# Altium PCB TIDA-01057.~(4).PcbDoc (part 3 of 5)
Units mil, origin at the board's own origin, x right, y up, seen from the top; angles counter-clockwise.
Board outline 4448 x 3930 mil, 4 copper layers (Layer 1 - Top Layer, Layer 2 - GND, Layer 3 - PWR, Layer 4 - Bottom Layer), stack 59.034 mil thick; 537 components, 284 nets, 1540 pads, 770 vias.
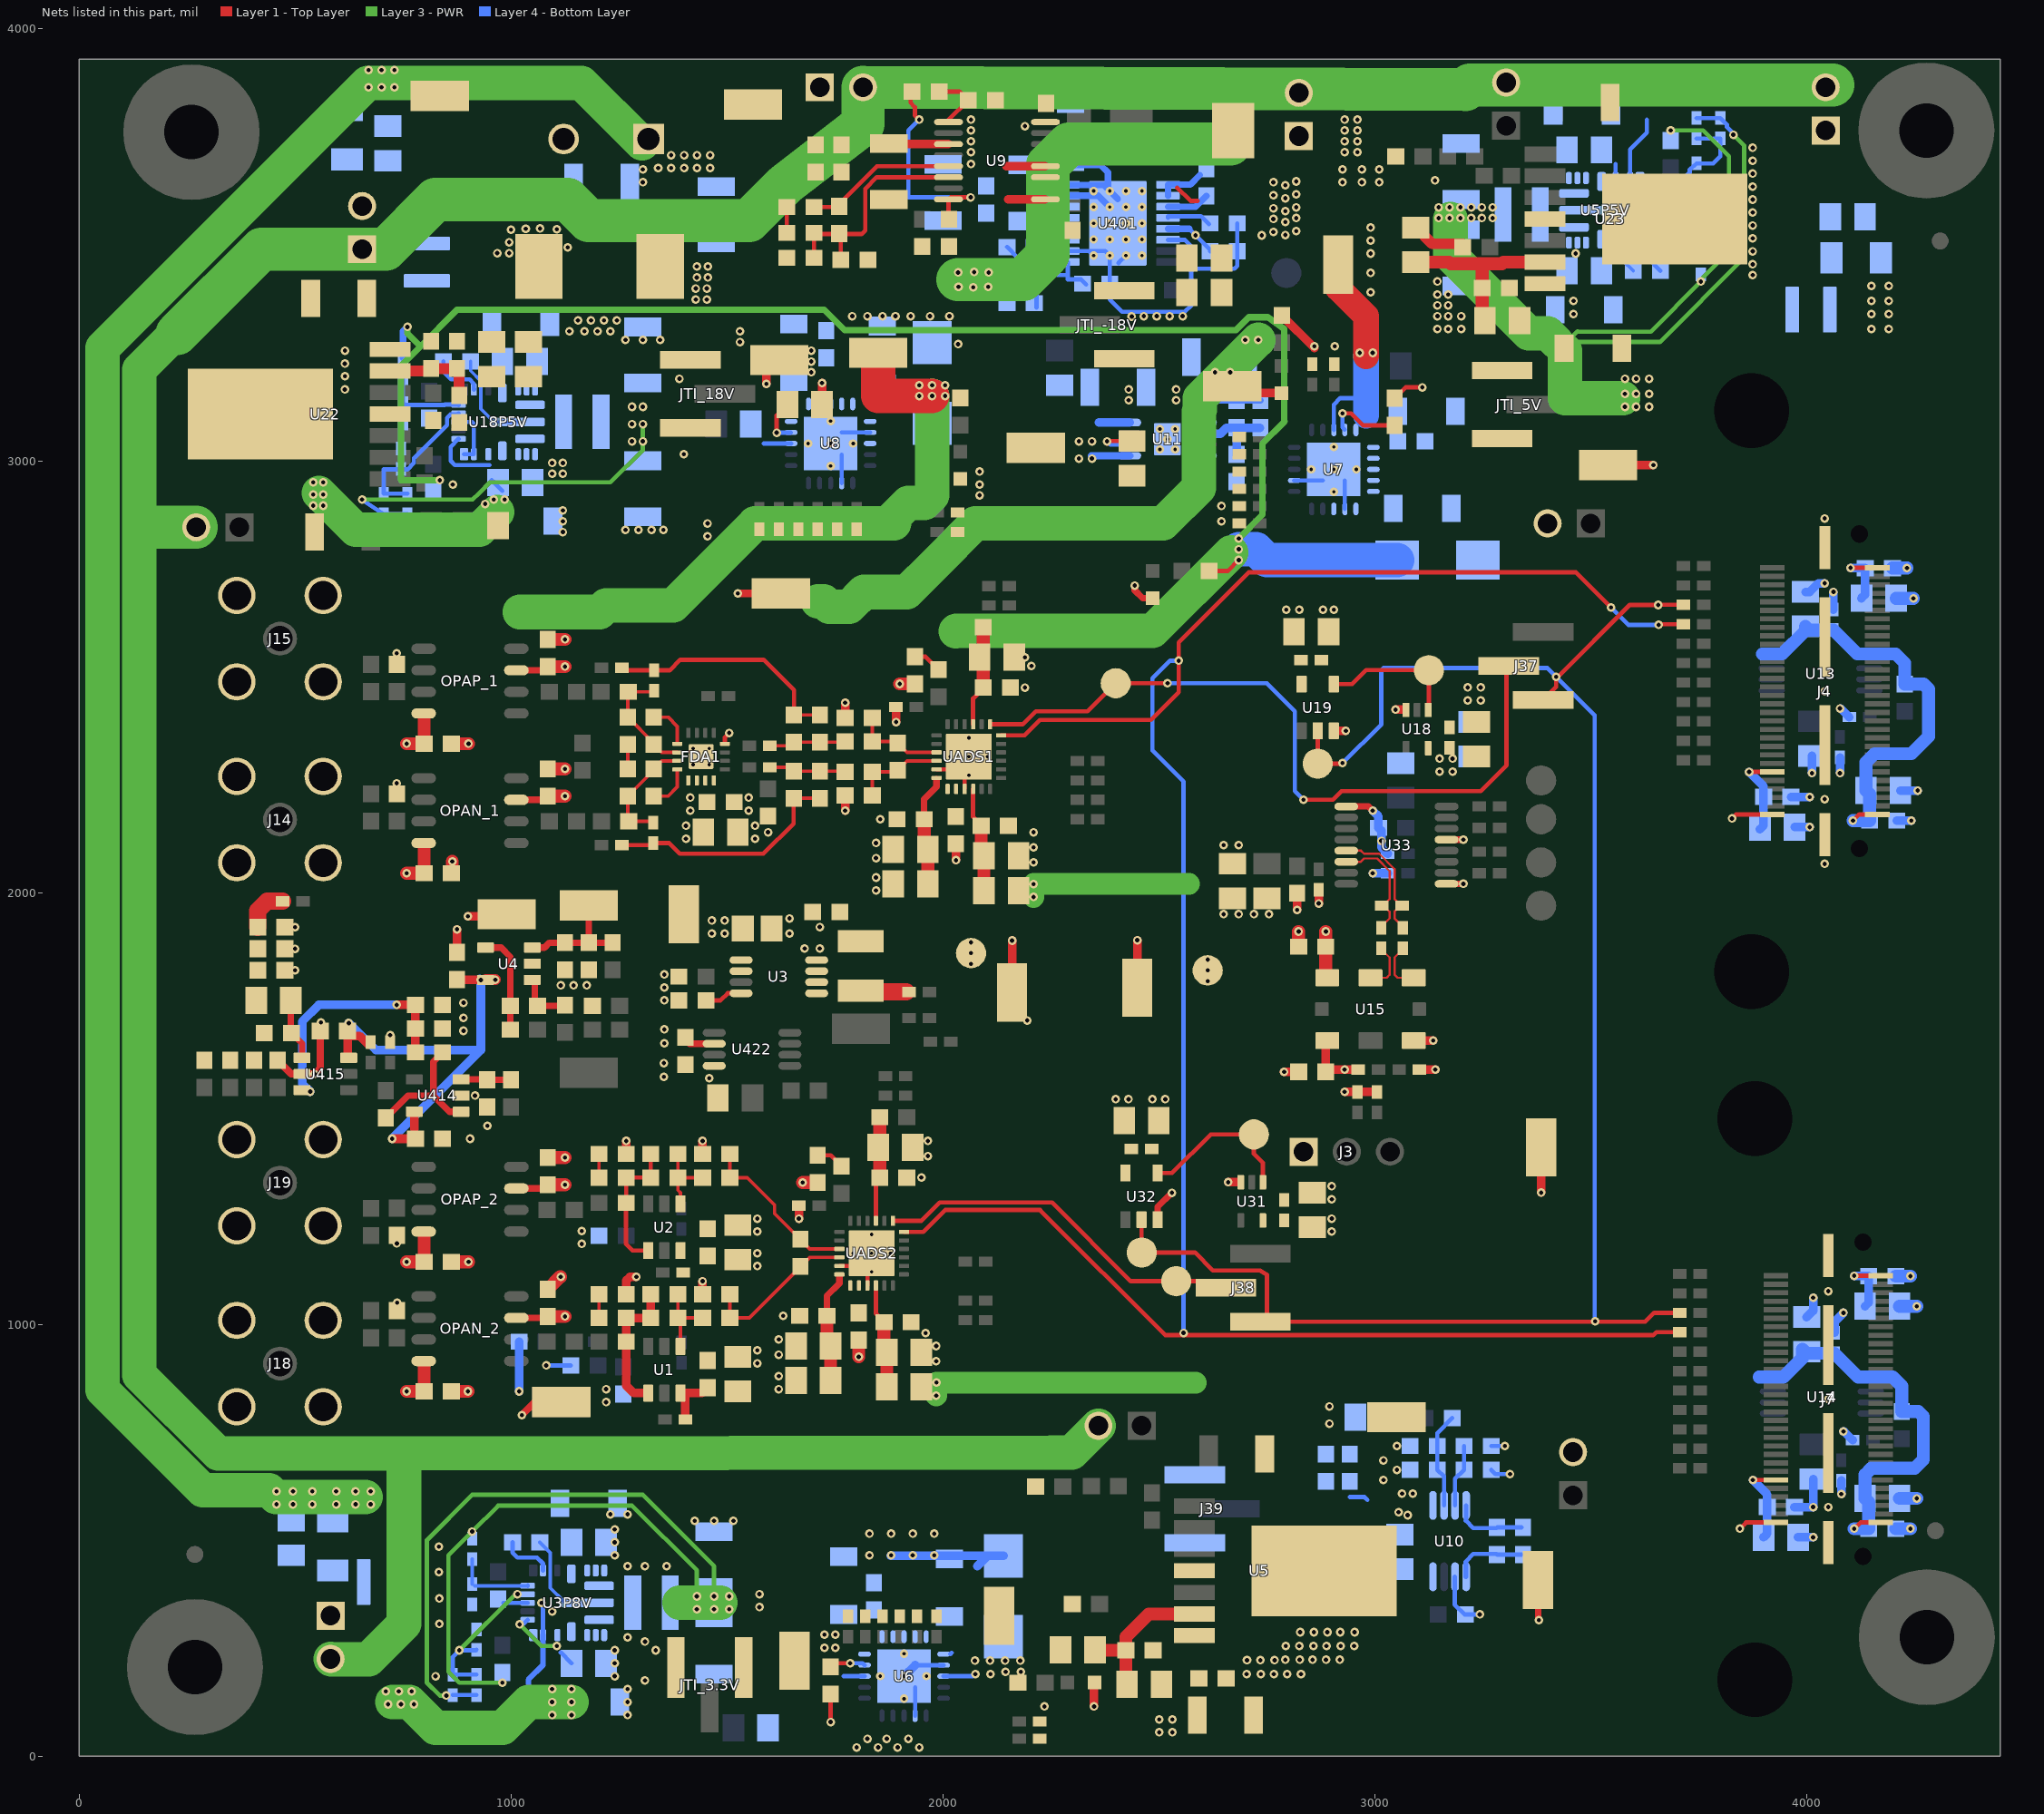
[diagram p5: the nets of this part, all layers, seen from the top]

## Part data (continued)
U422: "Low Noise, Very Low Drift, Precision Voltage Reference, -40 to 125 degC, 8-pin MSOP (DGK), Green (RoHS & no Sb/Br)", Alternate Manufacturer="Texas Instruments", Alternate PartNumber=Equivalent, Rating=Catalog, Supplier Part Number 1=296-24502-2-ND, Temp Coeff(Max)(ppm/ degree C)=3
UADS1 UADS2: "20-Bit, High-Speed SAR ADCs With Integrated Reference Buffer, Integrated LDO, and multiSPI Digital Interface, RGE0024H (VQFN-24)", Alternate Manufacturer="Texas Instruments", Alternate PartNumber=ADS8900BRGET
ZZ2 ZZ3 ZZ4: library part AssemblyNote, Alternate Manufacturer=-

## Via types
v1: diameter 20, hole 10, Layer 1 - Top Layer to Layer 4 - Bottom Layer, tented both sides, 382 vias
v2: diameter 20, hole 10, Layer 1 - Top Layer to Layer 4 - Bottom Layer, 258 vias
v3: diameter 20, hole 10, Layer 1 - Top Layer to Layer 4 - Bottom Layer, tented bottom, 57 vias
v4: diameter 19.68, hole 7.87, Layer 1 - Top Layer to Layer 4 - Bottom Layer, tented both sides, 48 vias
v5: diameter 20, hole 10, Layer 1 - Top Layer to Layer 4 - Bottom Layer, tented top, 19 vias
v6: diameter 19.68, hole 7.87, Layer 1 - Top Layer to Layer 4 - Bottom Layer, 6 vias

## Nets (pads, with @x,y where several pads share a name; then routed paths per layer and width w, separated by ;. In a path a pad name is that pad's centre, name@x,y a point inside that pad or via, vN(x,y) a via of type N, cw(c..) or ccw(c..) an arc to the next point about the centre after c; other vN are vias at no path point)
3.3V: C20.1 C61.1 C62.1 C94.2 C95.2 C290.1 C291.2 C338.1 C343.1 C344.2 C345.2 C346.2 C347.1 C353.1 L4.2 L7.1 L9.1 L10.2 L12.2 R46.2 R88.2 R89.2 R91.1 TP_3P3V.1 U6.1 U6.3 U6.20 U15.1@2890,1656.91 U15.6@2890,1802.58 U18.5 U19.5 U31.5 U32.5 | length 1429.3
  Layer 1 - Top Layer w20: U15.1@2886.5,1653.41 C62.1@2886.5,1584.75 2891.5,1589.75 v1(2930,1589.75) R91.1@2961.38,1589.75 ; v1(2930,1538.37) R88.2@2960,1538.37 R89.2@3005,1538.37
  Layer 1 - Top Layer w30: v1(2886.5,1909.74) C61.1@2886.5,1874.74 2886.5,1806.08 U15.6@2890,1802.58
  Layer 3 - PWR w50: v1(1984.45,834.74) 1984.45,864.19 v1(1985.25,865) 2585,865 ; v1(2210,1989.75) v1(2210,2019.75) 2210.25,2020 2570,2020
  Layer 4 - Bottom Layer w10: U6.3@2001.54,185 2070,185 v1(2075,190) ; 2017.09,236.18 2020,239.09
  other v1: 2110,190 2145.02,195 2180.21,195.21 2073.93,221.07 2108.93,221.07 2143.93,221.07 2178.93,221.07 3076.04,558 3055,565 2900.21,1214.75 2900.21,1244.75 2399.83,1521.3 2429.83,1521.3 2650,1949.74 2685,1949.74 2720,1949.74 2755,1949.74 3150,2280.04 3180,2280.04 3150,2310.04 3180,2310.04 2795,2654.75 2825,2654.75
3.8V: C17.1 C18.1 L19.2 TP_3P8V.1 U6.13 U6.15 U6.16 | length 48.5
  Layer 4 - Bottom Layer w10: 1770,185 U6.13@1818.46,185
  other v1: 1725.51,251 1751,251 1725.51,281 1751,281
5.5V: C13.1 C14.1 L18.2 TP_5P5V.1 U7.13 U7.15 U7.16 | length 441.6
  Layer 1 - Top Layer w60: TP_5P5V.1@2915,3400 2980,3335 2980,3242.5
  Layer 4 - Bottom Layer w10: U7.13@2905,3071.54 2905,3130 2920,3145 2960,3145
  Layer 4 - Bottom Layer w60: 2980,3105 L18.2@2980,3220 L18.2@2980,3242.5
  other v3: 2965,3250 2995,3250
5V: C3.2 C16.1 C85.1 C112.2 C116.2 C284.1 C304.1 C305.1 C320.2 C352.1 C449.2 C455.2 CR479.1 FDA1.5 FDA1.6 FDA1.7 FDA1.8 FDA1.12 L6.1 L8.1 R47.2 R453.1 RB18.2 REN0.1 REN1.1 RES18V.1 TP8.1 U1.6 U2.6 U3.1 U3.2 U4.5 U7.1 U7.3 U7.20 U414.5 U415.6 U422.2 | length 5611.6
  Layer 1 - Top Layer w10: U4.5@940.87,1797.6 U4.5@941.34,1798.08 ; FDA1.12@1495.12,2345.75 1495.12,2359.86 v1(1505,2369.75) ; R47.2@2616.5,2745 2660,2745 v1(2685,2770)
  Layer 1 - Top Layer w15: CR479.1@1413.8,1649.8 U422.2@1470.4,1649.8
  Layer 1 - Top Layer w20: C449.2@621.32,1679.02 C449.2@621.53,1678.81 ; U415.6@621.53,1616.87 C449.2@621.53,1678.81 ; R453.1@669.83,1647.64 649.46,1668 632.34,1668 C449.2@621.53,1678.81 ; v2(724.51,1429.75) C455.2@778.5,1429.75 ; 775.87,1452.38 U414.5@775.87,1492.34 ; C320.2@875,1796.24 876.36,1797.6 v1(930,1797.6) ; U1.6@1392.4,840.61 1442.36,840.61 C112.2@1455,853.25 ; REN0.1@1403.62,779.75 U1.6@1403.62,828.37
  Layer 1 - Top Layer w25: U4.5@941.34,1798.08 v1(963.52,1798.08)
  Layer 3 - PWR w15: v3(760,3310) 760,3295 790,3265 ; v2(835,2955) 745,2955 745,3220 790,3265 ; v1(2685,2820) 2740,2875 2740,3040 2789.9,3089.9 ; 2791.19,3091.19 2789.9,3089.9 ; 790,3265 875,3350 1725,3350 1772.5,3302.5 2678.25,3302.5 2708.25,3332.5 2751.75,3332.5 2789.9,3305.9 2789.9,3089.9
  Layer 3 - PWR w80: 2030,2604.75 2031.02,2605.77 2485.9,2605.77 2667.41,2787.28
  Layer 4 - Bottom Layer w15: RB18.2@750,3238.62 750,3300 v3(760,3310)
  Layer 4 - Bottom Layer w20: v2(624.28,1697.72) 686.76,1635.24 930,1635.24 ; v2(724.51,1429.75) 930,1635.24 ; v1@927.86,1799.75 v1(930,1797.6) 930,1635.24
  Layer 4 - Bottom Layer w80: v1(2685,2795) 2725,2795 2750,2770 C352.1@3051.5,2770
  other v1: 1620,849.75 1620,879.75 1570,1134.75 1570,1164.75 1464.79,1905.16 1494.79,1905.16 1464.79,1935.16 1494.79,1935.16 1845,2004.75 1845,2034.75 1405,2124.75 1405,2154.75 1415,2189.75 1415,2219.75
  other v2: 1355,1651 1355,1683
18.5V: C9.1 C10.1 L16.1 TP_18P5V.1 U8.13 U8.15 U8.16 | length 130.9
  Layer 1 - Top Layer w20: v2(1591,3178) 1591,3203 TP_18P5V.1@1621,3233
  Layer 4 - Bottom Layer w10: 1585,3040 U8.13@1648.46,3040
  other v2: 1695,3205 1695,3230 1695,3255
1050_3.3V: Cff3.1 Cout5.1 Cout6.1 JTI_3.3V.3 Rfbt3.2 U5.7
  other v2: 1800,20 1850,20 1895,20 1945,20 1825,40 1870,40 1920,40 2501,55 2531,55 2501,85 2531,85
1050_5V: Cff2.1 Cout4.1 JTI_5V.3 Rfbt2.2 U23.7
1050_18V: Cff.1 Cout1.1 Cout2.1 Cout3.1 JTI_18V.3 Rfbt.2 U22.7
1050_-18V: C34.2 C35.2 C37.2 C41.2 C42.2 C43.2 JTI_-18V.1 R42.1 R50.1 U9.9 U9.12 | length 176
  Layer 1 - Top Layer w20: 2147.2,3682.2 U9.12@2237.2,3682.2 ; 2151.2,3605.43 U9.9@2237.2,3605.43
+18V: C12.1 C79.2 C81.2 C104.2 C106.2 C351.1 OPAN_1.7 OPAN_2.7 OPAP_1.7 OPAP_2.7 R247.2 TP3.1 U8.1 U8.3 U8.20 | length 1981.4
  Layer 1 - Top Layer w15: OPAN_2.7@1012.28,1014.75 1081.5,1014.75 C104.2@1085,1018.25 ; OPAP_2.7@1012.28,1314.75 1081.5,1314.75 C106.2@1085,1318.25 ; OPAN_1.7@1012.28,2214.74 1076.5,2214.74 C81.2@1085,2223.25 ; OPAP_1.7@1012.28,2514.75 1076.5,2514.75 C79.2@1085,2523.25
  Layer 1 - Top Layer w30: C104.2@1085,1018.25 v1(1125,1018.25) ; C106.2@1085,1323.25 v1(1125,1323.25) ; C81.2@1085,2223.25 v1(1125,2223.25) ; C79.2@1085,2523.25 v1(1125,2523.25)
  Layer 1 - Top Layer w80: TP3.1@1850,3240 1850,3150 v1(1945,3150) v1(1975,3150)
  Layer 3 - PWR w80: 1020,2649.75 1205,2649.75 1220.25,2665 1375,2665 1565,2855 1887,2855 1887,2869.78 1919.22,2902 1957,2902 1975,2920 v1(1975,3150)
  other v1: 2005,3150 1945,3175 1975,3175 2005,3175
+24VDC: Cin.1 D1.1 JMTI_-18V.2 JPRI_-18V.2 JSI_3.3V.2 JSI_5V.2 JSI_18V.1 JZI_3.3V.2 JZI_5V.2 JZI_18V.2 | length 9642
  Layer 3 - PWR w10: 1810,3775 1815,3780
  Layer 3 - PWR w80: 227,3295 223,3295 139,3211 139,883 321.47,700.53 569.85,700.53 569.98,700.66 752,700.91 752,306 670,224 583,224 JSI_3.3V.2@582,225 ; 759,700.92 2250,703 2298,703 JZI_3.3V.2@2360,765
  Layer 3 - PWR w100: 149,2844 151,2846 JZI_18V.2@271,2846 ; 227,3295 422,3490 JSI_18V.1@655,3490 710,3490 825,3605 1131,3605 1180,3556 1551,3556 1635,3640 1810,3775 ; 1815,3780 JMTI_-18V.2@1815,3865 3210,3860 3220,3870 JSI_5V.2@4060,3870
  other v1: 1427.8,3373.53 1453.28,3373.53 1427.8,3399.02 1453.28,3399.02 1430,3424.51 1455.49,3424.51 1430,3450 1455.49,3450
+24VDC_IN: 24Vin.1 C1.1 D1.2 J8.2
  other v1: 968,3481 995.62,3481 1131,3494 995.62,3506 1000,3535 1106,3536 1034,3537 1067,3538
-0.2V: C23.1 C24.1 J39.1 L5.1 TP27.1
  other v1: 2895,770 2895,810
-18.5V: C354.1 L17.1 TP25.1 U11.5 U11.8 | length 159.8
  Layer 4 - Bottom Layer w17: v5@2343.39,3011.61 U11.5@2432.4,3011.61
  Layer 4 - Bottom Layer w20: 2361.61,3088.39 U11.8@2432.4,3088.39
  other v2: 2315,3045
  other v3: 2315,3005
  other v5: 2345,3005 2345,3045
-18V: C46.1 C47.1 C80.2 C82.2 C105.2 C107.2 D21.1 OPAN_1.4 OPAN_2.4 OPAP_1.4 OPAP_2.4 R43.2 TP26.1 U11.1 | length 2075.2
  Layer 1 - Top Layer w10: TP26.1@2695,3170 TP26.1@2708.26,3156.74
  Layer 1 - Top Layer w20: TP26.1@2708.26,3156.74 D21.1@2783.32,3156.74
  Layer 1 - Top Layer w30: v1(758.5,844.75) C105.2@798.5,844.75 OPAN_2.4@798.5,909.75 ; v1(758.5,1144.75) C107.2@798.5,1144.75 OPAP_2.4@798.5,1209.75 ; v1(758.5,2044.74) C82.2@798.5,2044.74 OPAN_1.4@798.5,2109.74 ; v1(758.5,2344.75) C80.2@798.5,2344.75 OPAP_1.4@798.5,2409.75
  Layer 3 - PWR w80: 1710,2674.75 1724.22,2674.75 1737.22,2661.75 1782.78,2661.75 1817.04,2696 1916,2696 1979.89,2759.89 2075,2855 2510,2855 2592.56,2937.56 2592.56,3114.78 2595,3117.22 2595,3145 v1(2730,3280)
  Layer 4 - Bottom Layer w15: 2629.55,3139.55 C46.1@2735,3139.55
  Layer 4 - Bottom Layer w20: U11.1@2607.6,3094.29 2607.6,3101.44 2607.6,3117.6 2629.55,3139.55
  other v2: 2700,3280
  other v5: 2630,3205 2665,3205
AGND: C3.1 C4.2 C71.1 C72.1 C79.1 C80.1 C81.1 C82.1 C84.2 C85.2 C88.1 C89.2 C90.2 C91.1 C92.2 C93.2 C96.1 C97.1 C104.1 C105.1 C106.1 C107.1 C108.2 C109.2 C112.1 C115.2 C116.1 C117.2 C118.2 C119.2 C120.1 C121.2 C122.2 C284.2 C287.2 C288.2 C289.2 C304.2 C305.2 C306.2 C307.2 C308.2 C318.2 C320.1 C321.2 C449.1 C453.2 C454.2 C455.1 C457.2 C458.2 C459.2 CR479.2 CR481.2 FDA1.17 J14.2 J14.3 J14.4 J14.5 J15.2 J15.3 J15.4 J15.5 J18.2 J18.3 J18.4 J18.5 J19.2 J19.3 J19.4 J19.5 NT1.1 NT2.1 R3.1 R4.2 R110.1 R112.1 R113.1 R217.1 R268.1 R269.1 R284.1 R288.1 R454.1 R488.1 R491.1 TPAGND1.1 TPAGND2.1 TPAGND3.1 TPAGND4.1 TPAGND.1 U3.7 U3.8 U4.2 U414.2 U415.2 U422.4 UADS1.11 UADS1.15 UADS1.25 UADS2.11 UADS2.15 UADS2.25 | length 1836.9
  Layer 1 - Top Layer w10: UADS2.11@1760.2,1135.22 UADS2.25@1805.47,1135.22 ; UADS2.15@1825.16,1089.94 UADS2.25@1825.16,1154.9 ; UADS1.11@1985.2,2285.22 2030.47,2285.22 UADS1.25@2050.16,2304.9 ; UADS1.15@2050.16,2239.94 UADS1.25@2050.16,2304.9 ; v4(2060,2314.75) UADS1.25@2050.16,2304.9
  Layer 1 - Top Layer w17: R491.1@459.7,1611.24 491.2,1579.75 U415.2@515.87,1579.75 ; U415.2@513.26,1579.47 545.28,1579.47 558.33,1592.52 C449.1@558.33,1679.02 ; v1(1025,789.75) 1055,819.75 TPAGND4.1@1116.5,819.75 ; v2(1525,2692.75) TPAGND1.1@1625,2692.75
  Layer 1 - Top Layer w20: C320.1@875,1861.24 v1(875,1914.75) ; v1(900,1944.75) TPAGND3.1@1000,1944.75 ; R113.1@1266.5,1069.75 1266.5,1101.24 1275,1109.75 v1(1290,1109.75) ; R112.1@1266.5,1394.75 v5(1266.5,1424.75) ; C118.2@1443.5,1069.75 v1(1443.5,1099.75) ; C117.2@1443.5,1394.75 v1(1443.5,1424.75) ; v1(1666.38,1244.75) R288.1@1666.38,1274.75 ; v1(1773.5,2189.75) C89.2@1773.5,2224.75 ; C90.2@1773.5,2404.75 v1(1773.5,2439.75) ; v1(1891.38,2394.75) R284.1@1891.38,2429.75 ; v1(2030,2074.75) C88.1@2030,2113.25 ; TPAGND2.1@2160,1788.75 v1(2160,1888.75)
  Layer 1 - Top Layer w30: C105.1@861.5,844.75 v1(900,844.75) ; C107.1@861.5,1144.75 v1(901.5,1144.75) ; C82.1@861.49,2044.74 863.99,2047.25 v1(863.99,2071.94) ; C80.1@861.5,2344.75 v1(901.5,2344.75) ; C104.1@1085,1081.24 1113.5,1109.75 v1(1115,1109.75) ; C106.1@1085,1386.24 v1(1125,1386.24) ; C81.1@1085,2286.24 v1(1125,2286.24) ; C79.1@1085,2586.24 v1(1125,2586.24) ; v1(1675,1328.25) R269.1@1710,1328.25 ; v1(1805,924.75) C119.2@1805,963.25 ; v1(1900,2483.25) R268.1@1935,2483.25
  Layer 4 - Bottom Layer w10: v1(1081.5,904.75) R110.1@1138.5,904.75
  Layer 4 - Bottom Layer w20: v1(1018.5,844.75) 1018.5,904.75 C108.2@1018.5,959.75
  other v1: 1220,819.75 1220,849.75 1570,909.75 1984.45,914.74 1620,929.75 1570,939.75 1984.45,949.74 1620,964.75 1960,979.75 1630,1019.75 1163.5,1186.24 735.46,1187.35 1570,1214.75 1163.5,1216.24 1570,1244.75 1950,1339.75 1965,1389.75 1965,1424.75 2195,1703.75 1354.79,1750.16 1354.79,1780.16 1115,1785.01 1145,1785.01 1175,1785.01 1354.79,1810.16 2065,1834.75 2065,1859.75 1679.79,1870.16 1714.79,1870.16 2065,1884.75 1644.79,1905.16 1714.79,1920.16 1644.79,1940.16 2210,2069.75 1845,2079.75 2210,2104.75 1845,2114.75 1565,2124.75 1595,2139.75 2210,2139.75 1565,2154.75 1855,2169.75 1550,2189.75 1550,2219.75 2190,2474.75 2205,2524.75 2190,2544.75
  other v2: 905,1429.75 1459,1570 1354,1573 1354,1605 890,1679.75 559.83,1699.02 890,1709.75 500,1819.75 500,1869.75 500,1919.75
  other v4: 1835,1121.44 1791.69,1164.75 1835,1164.75 1878.31,1164.75 1835,1208.05 2060,2271.44 1421.3,2296.04 1458.7,2296.04 2016.69,2314.75 2103.31,2314.75 1421.3,2333.45 1458.7,2333.45 2060,2358.05
  other v5: 736,1050 945,1459.75 916.46,1529.75 545,1579.75 720,1669.75 890,1744.75 735,2253 735,2554
BCLK0_N: C64.1 U15.5@2990,1802.58 | length 116.9
  Layer 1 - Top Layer w5: U15.5@2990,1802.58 3027.33,1802.58 3034.5,1809.75 3034.5,1849.25 3015,1868.75 C64.1@3015,1871.12
BCLK0_P: C63.1 U15.4@3090,1802.58 | length 116.9
  Layer 1 - Top Layer w5: C63.1@3065,1871.13 3065,1868.75 3045.5,1849.25 3045.5,1809.75 3052.67,1802.58 U15.4@3090,1802.58
BCLK1_N: C64.2 R92.1 U33.6 | length 271.2
  Layer 1 - Top Layer w5: U33.6@2933.86,2071.36 2967.62,2071.36 2975,2078.75 3005.44,2078.75 3034.5,2049.68 3034.5,1985.25 R92.1@3019,1969.75 ; C64.2@3015,1918.37 3015,1920.74 3034.5,1940.25 3034.5,1955.25 3020,1969.75 R92.1@3019,1969.75 ; R92.1@3016.38,1969.75 R92.1@3019,1969.75
BCLK1_P: C63.2 R92.2 U33.5 | length 287.9
  Layer 1 - Top Layer w5: U33.5@2933.86,2096.95 2967.8,2096.95 2975,2089.75 3010,2089.75 3045.5,2054.24 3045.5,1985.25 3061,1969.75 R92.2@3063.63,1969.75 ; R92.2@3059,1969.75 3045.5,1956.25 3045.5,1940.25 3065,1920.75 C63.2@3065,1918.37
CONVST: J37.3 J38.3 R67.1 R78.1 TP7.1 TP35.1 U19.2 U32.2 | length 4240.8
  Layer 1 - Top Layer w10: TP35.1@2459.83,1166.75 U32.2@2459.83,1242.14 ; TP35.1@2460.3,1166.28 2583.47,1166.28 2625,1124.75 2734,1124.75 2750,1114.69 2750,1021.04 J38.3@2734.96,1006.01 3626.01,1006.01 3646.69,1026.69 R78.1@3706.4,1026.69 R78.1@3706.35,1026.75 ; U19.2@2867.81,2374.41 TP7.1@2867.81,2298.54 2923.8,2298.54 v2(2925,2299.75) ; J37.3@3389.96,2446.01 3420,2476.04 v2(3420,2499.75) 3423.75,2499.75 3590,2666 v2(3656,2666) 3656.39,2666.39 R67.1@3714.12,2666.39
  Layer 4 - Bottom Layer w10: v2(2925,2299.75) 3015,2389.75 3015,2514.75 3020,2519.75 3400,2519.75 v2(3420,2499.75) 3509,2410.75 3509,1008 v2(3510,1007)
CONVST_TO_DIF_ADC: J37.2 TP1.1 UADS1.1 | length 1720.7
  Layer 1 - Top Layer w10: UADS1.1@2109.21,2389.55 2184.8,2389.55 2215,2419.75 2335,2419.75 TP1.1@2400,2484.75 v1(2520,2484.75) ; v1(2835,2214.75) 2902.63,2214.75 2922.63,2234.75 3245,2234.75 3305,2294.75 3305,2519.71 J37.2@3310.04,2524.75
  Layer 4 - Bottom Layer w10: v1(2520,2484.75) 2750,2484.75 2815,2419.75 2815,2234.75 v1(2835,2214.75)
CONVST_TO_SE_ADC: J38.2 TP4.1 UADS2.1 | length 870.1
  Layer 1 - Top Layer w10: UADS2.1@1884.21,1239.55 1949.8,1239.55 1992.25,1282 2252.75,1282 2435,1099.75 TP4.1@2540,1099.75 2640.04,1099.75 J38.2@2655.04,1084.75
CONVSTN_DIF: TP2.1 U18.1 U19.4 | length 326.1
  Layer 1 - Top Layer w10: U19.4@2905.21,2482.68 2947.64,2482.68 2980,2515.04 TP2.1@3125,2515.04 3125,2424.44 U18.1@3123.4,2422.84
CONVSTN_SE: TP34.1 U31.1 U32.4 | length 379.1
  Layer 1 - Top Layer w10: U32.4@2497.23,1350.41 2530.67,1350.41 2620,1439.75 TP34.1@2720,1439.75 2720,1394.75 2740.8,1373.94 U31.1@2740.8,1329.04
CSN: R68.1 R79.1 UADS1.24 UADS2.24 | length 5423.1
  Layer 1 - Top Layer w10: UADS2.24@1909.8,1213.96 1954.21,1213.96 2005,1264.75 2225,1264.75 2515,974.75 3644.75,974.75 3651.69,981.69 R79.1@3706.4,981.69 ; UADS1.24@2134.8,2363.96 2189.21,2363.96 2225,2399.75 2481.51,2399.75 2546,2464.24 v2(2546,2537) 2546,2579.53 2707.86,2741.39 3465.61,2741.39 v2(3547,2660) ; v2(3657,2620) 3658.39,2621.39 R68.1@3714.12,2621.39 R68.1@3713.73,2621
  Layer 4 - Bottom Layer w10: v2(2546,2537) 2526,2537 2485,2496 2485,2329 2557,2257 v2(2557,980) v2@2557,976 ; v2(3547,2660) 3587,2620 v2(3657,2620)
EVM_DVDD_0: C22.1 C266.1 J4.50 | length 204
  Layer 1 - Top Layer w10: v1(3866.7,2279.29) J4.50@3920.51,2279.29
  Layer 4 - Bottom Layer w20: v1(3866.7,2279.29) 3900.02,2245.96 3900.02,2154.9 C22.1@3891.52,2146.39
EVM_DVDD_1: C21.1 C268.1 J7.50 | length 203.5
  Layer 1 - Top Layer w10: v1(3875.21,639.59) J7.50@3928.52,639.59
  Layer 4 - Bottom Layer w20: v1(3875.21,639.59) 3908.53,606.27 C268.1@3908.53,576.69 3908.53,515.2 C21.1@3900.03,506.69
EVM_ID_PWR_0: C53.2 C58.1 C259.1 C271.1 J4.59 R64.2 U13.1 U13.8 | length 1025.4
  Layer 1 - Top Layer w10: v1(4107.01,2166.39) 4121.4,2180.79 J4.59@4163.51,2180.79
  Layer 4 - Bottom Layer w30: 3897,2552.4 3943,2552.4 3997,2606.4 C271.1@3997,2616.4 4005.63,2607.77 C53.2@4062,2607.77 4117,2552.77 4117,2552.4 4206,2552.4 4227.01,2531.39 R64.2@4227.01,2482.89 4270.51,2482.89 4282.01,2471.39 4282.01,2361.39 4242.01,2321.39 4157.01,2321.39 4137.01,2301.39 C58.1@4137.01,2236.39 4145.51,2227.89 C259.1@4145.51,2166.39 v1(4107.01,2166.39)
EVM_ID_PWR_1: C55.2 C60.1 C260.1 C272.1 J7.59 R87.2 U14.1 U14.8 | length 995.7
  Layer 1 - Top Layer w10: v1(4110.02,526.69) 4124.42,541.09 J7.59@4171.52,541.09
  Layer 4 - Bottom Layer w30: 3890.02,877.69 3946.04,877.69 3990.02,921.68 3990.02,941.69 3998.65,933.07 4063.65,933.07 4119.02,877.69 4199.02,877.69 4220.03,856.69 R87.2@4220.03,798.19 4258.53,798.19 4270.02,786.69 4270.02,686.69 4250.02,666.69 4150.02,666.69 4135.03,651.7 C60.1@4135.03,596.69 4143.54,588.19 C260.1@4143.54,526.69 v1(4110.02,526.69)
EVM_REG_5V5_0: C57.1 C267.1 J4.1 | length 169.3
  Layer 1 - Top Layer w10: v1(4101.51,2752.09) J4.1@4163.51,2752.09
  Layer 4 - Bottom Layer w20: v1(4101.51,2752.09) 4134.34,2752.09 4135.02,2751.4 4135.02,2689.89 C57.1@4126.52,2681.39
EVM_REG_5V5_1: C59.1 C269.1 J7.1 | length 168.8
  Layer 1 - Top Layer w10: v1(4110.02,1112.39) J7.1@4171.52,1112.39
  Layer 4 - Bottom Layer w20: v1(4110.02,1112.39) 4142.85,1112.39 C269.1@4143.54,1111.71 4143.54,1050.2 C59.1@4135.03,1041.69
FB_3P3V: Cff3.2 Rfbb3.2 Rfbt3.1 U5.6 | length 358.8
  Layer 1 - Top Layer w30: Rfbb3.2@2353,245 Rfbt3.1@2423.5,245 ; Cff3.2@2423.5,168.5 Rfbt3.1@2423.5,245 ; U5.6@2582.37,329 2476.5,329 2423.5,276.01 Rfbt3.1@2423.5,245
FB_5V: Cff2.2 Rfbb5.2 Rfbt2.1 U23.6 | length 423.7
  Layer 1 - Top Layer w30: Rfbb5.2@3095,3460 3171.83,3460 3175.53,3456.3 3294.47,3456.3 3298.17,3460 U23.6@3394.37,3460 ; Cff2.2@3248.5,3331.5 Rfbt2.1@3248.5,3400 3248.5,3452.8
FB_18V: Cff.2 Rfbb.2 Rfbt.1 U22.6 | length 213.9
  Layer 1 - Top Layer w25: U22.6@719.63,3208 Rfbt.1@809.5,3208 ; Rfbt.1@815,3213.5 Cff.2@875,3213.5 880,3208.5 Rfbb.2@880,3151.5
GND: C1.2 C9.2 C10.2 C11.2 C12.2 C13.2 C14.2 C15.1 C16.2 C17.2 C18.2 C19.1 C20.2 C21.2 C22.2 C23.2 C24.2 C25.2 C26.2 C27.2 C28.2 C31.2 C32.2 C33.2 C41.1 C42.1 C45.2 C47.2 C53.1 C54.1 C55.1 C56.1 C57.2 C58.2 C59.2 C60.2 C61.2 C62.2 C94.1 C95.1 C259.2 C260.2 C261.2 C262.2 C266.2 C267.2 C268.2 C269.2 C271.2 C272.2 C290.2 C291.1 C338.2 C339.2 C340.2 C343.2 C344.1 C345.1 C346.1 C347.2 C348.2 C349.2 C350.2 C351.2 C352.2 C353.2 C354.2 C355.2 C356.2 C357.2 C358.2 C359.2 C360.2 C362.2 C364.2 C366.2 C367.2 C368.2 C369.2 C370.2 C371.2 C372.2 C375.2 C376.2 C378.2 C379.2 C380.2 C381.2 C382.2 C383.2 C384.2 C388.2 C389.2 C391.2 C401.2 C402.2 C405.1 C406.1 C409.1 Cin1.2 Cin2.2 Cin3.2 Cin.2 Cout1.2 Cout2.2 Cout3.2 Cout4.2 Cout5.2 Cout6.2 Css2.2 Css3.2 Css.1 CVCC3V.2 CVCC5V.2 CVCC18V.2 D14.1 D18.1 D22.1 GNDin.1 J3.1 J4.60 J4.MP1 J4.MP2 J4.MP3 J4.MP4 J5.2 J6.2 J7.60 J7.MP1 J7.MP2 J7.MP3 J7.MP4 J8.1 J39.3 L1.2 L401.2 NT1.2 NT2.2 R8.1 R9.1 R10.1 R11.1 R12.1 R13.1 R14.1 R15.1 R17.1 R18.1 R19.1 R20.1 R21.1 R24.1 R25.1 R26.1 R27.1 R29.1 R30.1 R31.1 R32.1 R33.1 R34.1 R35.1 R36.1 R41.2 R44.1 R90.1 R246.2 R279.1 R280.1 R290.1 R294.1 R297.1 R402.2 Renb2.1 Renb3.1 Renb.1 Rfbb3.1 Rfbb5.1 Rfbb.1 TPGND1.1 TPGND2.1 TPGND3.1 TPGND4.1 TPGND.1 U3P8V.5 U3P8V.6 U3P8V.7 U3P8V.8 U3P8V.10 U3P8V.11 U3P8V.12 U3P8V.13 U3P8V.16 U3P8V.17 U3P8V.20 U5.4 U5.8 U5P5V.5 U5P5V.6 U5P5V.7 U5P5V.8 U5P5V.10 U5P5V.11 U5P5V.12 U5P5V.13 U5P5V.16 U5P5V.17 U5P5V.20 U6.2 U6.7 U6.17 U6.18 U6.19 U6.21 U7.2 U7.7 U7.17 U7.18 U7.19 U7.21 U8.2 U8.7 U8.17 U8.18 U8.19 U8.21 U9.11 U10.2 U10.5 U11.4 U11.9 U15.3@3090,1656.91 U18.3 U18P5V.5 U18P5V.6 U18P5V.7 U18P5V.8 U18P5V.10 U18P5V.11 U18P5V.12 U18P5V.13 U18P5V.16 U18P5V.17 U18P5V.20 U19.3 U22.4 U22.8 U23.4 U23.8 U31.3 U32.3 U33.1 U33.9 U33.13 U401.5 | length 9291.5
  Layer 1 - Top Layer w10: v1(1740,78.98) C19.1@1740,137.48 ; 2542,3633 2573.11,3601.89 2590,3601.89 ; C15.1@3046.02,3145.15 3070.87,3170 v1(3110,3170) ; v1(3827.01,2171.39) 3836.4,2180.79 J4.60@3920.51,2180.79 ; v1(3845.02,526.69) 3859.42,541.09 J7.60@3928.52,541.09
  Layer 1 - Top Layer w15: v1(2444,2711) 2444,2700 2462.5,2681.5 D18.1@2486,2681.5 ; U32.3@2497.23,1242.14 2497.23,1271.98 v1(2530,1304.75) ; U33.1@2933.86,2199.31 2985.43,2199.31 v1(2995,2189.75) ; U33.9@3166.14,2020.18 v1(3205,2020.18) ; U33.13@3166.14,2122.54 v1(3205,2122.54) ; TPGND1.1@3378.02,408 3378.02,316.98 v1(3380,315)
  Layer 1 - Top Layer w20: C11.2@1720,3130 v1(1720,3180) ; v1(2350,115) D14.1@2350,160 ; TPGND2.1@2450,1779.75 v1(2450,1889.75) ; v1(2660.21,1329.04) U31.3@2685.21,1329.04 ; R246.2@2785,3336.5 v5@2860,3261.5 ; v1(2790.01,1584.75) C62.2@2823.5,1584.75 ; v1(2820,1959.75) C339.2@2820,1998.25 ; v1(2870,1974.74) C340.2@2870,2006.13 ; U19.3@2905.21,2374.41 v1(2932.81,2374.41) ; v1(3047.81,2423.57) U18.3@3067.81,2423.57 ; U15.3@3090,1656.91 v1(3135,1656.91) ; R90.1@3103.62,1589.75 v1(3140,1589.75) ; v1(3385,1305) TPGND4.1@3385,1425 ; TPGND3.1@3540,2990 v1(3645,2990)
  Layer 1 - Top Layer w25: Rfbb5.1@3095,3540 3132.5,3502.5 3203.5,3502.5 Css2.2@3203.5,3495
  Layer 1 - Top Layer w30: C61.2@2823.5,1874.74 v1(2823.5,1909.74)
  Layer 3 - PWR w80: 663.55,600 455,600 439.47,615.53 286.26,615.53 54,847.79 54,3261 668,3875 1163.43,3875 J8.1@1303.43,3735
  Layer 4 - Bottom Layer w10: CVCC18V.2@810,3098.5 CVCC18V.2@818.5,3090 ; U18P5V.20@878.46,3090 910,3090 913.9,3086.1 U18P5V.16@913.9,3015.2 U18P5V.17@891.26,3015.2 ; CVCC3V.2@981.81,355 U3P8V.20@1038.46,355 ; v2(1070,355) 1073.9,351.1 U3P8V.16@1073.9,280.2 ; U8.7@1765.59,2948.46 U8.21@1765.59,3014.41 ; U8.21@1765.59,3065.59 U8.2@1831.54,3065.59 ; U6.7@1935.59,93.46 U6.21@1935.59,159.41 ; U6.21@1935.59,210.59 U6.2@2001.54,210.59 ; 2570,3537.2 2618.5,3488.7 C405.1@2618.5,3485 ; U7.7@2813.46,2954.41 U7.21@2879.41,2954.41 ; U7.2@2930.59,2888.46 U7.21@2930.59,2954.41 ; 2941.72,599.98 2976.04,599.98 2983.02,593 ; U10.2@3184.9,415.32 3184.9,350.64 3185.81,349.72 ; U10.2@3185.81,415.32 3185.81,349.72 ; v1(3243.02,328) 3207.53,328 3185.81,349.72 ; C27.2@3269.51,663 3279.51,653 v1(3313.02,653) ; C28.2@3269.51,718 v1(3301.04,718) ; 3591.1,3583.9 3595,3580 U5P5V.20@3626.54,3580 ; U5P5V.16@3591.1,3654.8 3591.1,3721.1 3630,3760 3630,3790 ; CVCC5V.2@3686.5,3580 CVCC5V.2@3695,3571.5
  Layer 4 - Bottom Layer w13: 1040,80 1040,177 1073.9,210.9 U3P8V.16@1073.9,280.2
  Layer 4 - Bottom Layer w15: U401.5@2521.14,3537.2 2570,3537.2
  Layer 4 - Bottom Layer w20: v1@1878.5,463.5 C353.2@2140,463.5 ; v4(1910,185) U6.21@1935.59,210.59 ; 2080,440 C353.2@2103.5,463.5 ; v1(2995,2044.75) C350.2@3029.93,2044.75 ; v1(2995,2189.75) 3008.5,2176.24 C348.2@3008.5,2149.75 3015,2143.25 v1(3015,2119.75) 3015,2104.68 C349.2@3029.93,2089.75 ; C266.2@3963.5,2221.39 v1(4007.01,2221.39) ; C268.2@3971.52,576.69 v1(4015.02,576.69) C261.2@4015.02,641.69 ; C22.2@3972.01,2151.39 v1(4007.01,2151.39) ; C21.2@3980.03,506.69 v1(4015.02,506.69) ; C271.2@3997,2696.4 4007.01,2696.4 4027,2716.39 v1(4041.52,2716.39) ; C272.2@4000.02,1016.69 4015.02,1031.69 v1(4015.02,1061.69) ; v1(4012.01,2276.39) C262.2@4012.01,2316.39 ; C53.1@4062,2655.02 v1(4062,2696.4) ; C55.1@4065.02,980.32 4065.02,1006.69 v1(4085.02,1026.69) ; v1(4077.01,2276.39) C54.1@4077.01,2312.77 ; v1@4078.39,2426.39 R279.1@4098.39,2406.39 ; v1(4080.03,606.7) C56.1@4080.03,638.07 ; v1(4085.02,751.69) 4086.4,751.69 R280.1@4106.4,731.69 ; C259.2@4208.5,2166.39 v1(4242.01,2166.39) ; C58.2@4217.01,2236.39 v1(4257.01,2236.39)
  Layer 4 - Bottom Layer w30: C267.2@4198.5,2751.39 v1(4232.01,2751.39) ; C260.2@4206.53,526.69 v1(4240.04,526.69) ; C269.2@4206.53,1111.71 v1(4240.03,1111.71) ; C57.2@4207.01,2681.39 v1(4247.01,2681.39) ; C60.2@4215.03,596.69 v1(4255.04,596.69) ; C59.2@4215.03,1041.69 v1(4255.04,1041.69)
  other v1: 2235,115 1310,175 1575,345 1575,375 1830,465 1880,465 1930,465 1980,465 1240,495 1830,515 1880,515 1930,515 1980,515 1240,525 1425,545 1470,545 1515,545 1270,560 4050.03,576.7 640,583 675,583 3063.02,608 3088.02,608 457,613 495,613 540,613 595,613 640,613 675,613 3020,639.63 3051.04,663 3020,685 3051.04,718 4050.03,826.7 4050.03,1076.7 2900.21,1289.75 2900.21,1319.75 2484.83,1521.3 2514.83,1521.3 2613,1794.75 2613,1819.75 2613,1844.75 4041.51,2066.39 2650,2109.74 2685,2109.74 4041.51,2216.39 4077.01,2426.39 3215,2445.04 3245,2445.04 4041.52,2466.39 3215,2475.04 3245,2475.04 2880,2654.75 2905,2654.75 1295,2840 1353,2840 1120,2860 4041.51,2866.39 2085,2920 1095,2970 1120,2970 1095,2995 2430,3140 2540,3140 2430,3165 2540,3165 2907,3265 1530,3275 1135,3300 1230,3300 1530,3300 4150,3305 4190,3305 1155,3325 1185,3325 1215,3325 1245,3325 1790,3335 1825,3335 1860,3335 1890,3335 4150,3340 4190,3340 4150,3370 4190,3370 4150,3405 4190,3405 1305,3645 1305,3675 1340.69,3677.89 1370.69,3677.89 1400.69,3677.89 1430.69,3677.89 1460.69,3677.89 1370.69,3707.89 1400.69,3707.89 1430.69,3707.89 1460.69,3707.89 2930,3715 2960,3715 2065,3740 2065,3765 2930,3765 2065,3790 730,3865 670,3905
  other v2: 1270,95 1270,125 1270,155 825,185 2703,190 2736,190 2766,190 2797,190 2829,190 2704,222 2735,222 2768,222 2793,223 2826,223 2856,223 2887,223 2919,223 2794,255 2825,255 2858,255 2888,255 2921,255 2952,255 1310,265 1270,275 2827,287 2859,287 2890,287 2920,287 2953,287 834,306 1095,335 834,365 833,426 1310,440 833,485 1455,2825 1265,2840 1455,2855 865,2945 1120,2995 1400,3015 615,3165 615.3,3196 615,3225 615.3,3255 1305,3280 1200,3300 3145,3305 3170,3305 3200,3305 1925,3335 1970,3335 3170,3335 3200,3335 3145,3360 3460,3370 3145,3385 2990,3390 3145,3415 3875,3430 2990,3435 3875,3455 3875,3485 2990,3510 3875,3515 2585,3522.2 2738,3522 2793,3523 2765,3530 2818,3532 2990,3540 3875,3545 2793,3553 2765,3560 2818,3562 3875,3575 2793,3578 2765,3585 2818,3587 3875,3605 2793,3608 2765,3615 2818,3617 3875,3635 2793,3638 2765,3645 2925,3645 2970,3645 3010,3645 2818,3647 3875,3665 2925,3675 2970,3675 3010,3675 3875,3695 3875,3725 2930,3740
  other v3: 1240,185 1240,215 1240,245 1335,245 1270,440 1360,440 1240,465 1230,560 457,583 495,583 540,583 595,583 1120,2835 1325,2840 1120,2885 1390,3190 2035,3270 1265,3280 1345,3280 1170,3300 2015,3335 3145,3335 3460,3340 3170,3360 3170,3385 2990,3480 3465,3480 3139.15,3649.13 2065,3687 2065,3715 2960,3740 2960,3765 2190,3775 2930,3790 2960,3790 670,3865 700,3865 700,3905 730,3905
  other v4: 1910,132.83 1855,185 1962.17,185 1910,237.17 2905,2927.83 2852.83,2980 2905,2980 2957.17,2980 1740,2987.83 2502.28,3026.38 2537.72,3026.38 2905,3032.17 1687.83,3040 1740,3040 1792.17,3040 2520,3050 2502.28,3073.62 2537.72,3073.62 1740,3092.17
  other v5: 2645,2860 2645,2895 2085,2945 2085,2975 2860,3265
NetC4_1: C4.1 U3.4 | length 87.8
  Layer 1 - Top Layer w10: C4.1@1451.5,1750.16 1484.79,1750.16 1501.4,1766.77 U3.4@1532.4,1766.77
NetC5_1: C5.1 R56.1 U3.5 U3.6 | length 100.2
  Layer 1 - Top Layer w40: C5.1@1814.75,1769.75 R56.1@1915,1769.75
NetC5_2: C5.2 R4.1
NetC11_1: C11.1 U8.14 | length 108.2
  Layer 1 - Top Layer w10: v1(1615,3065) 1615,3105 C11.1@1640,3130
  Layer 4 - Bottom Layer w10: v1(1615,3065) U8.14@1647.87,3065
NetC15_2: C15.2 U7.14 | length 172.5
  Layer 1 - Top Layer w10: v1(2925,3110) 2945,3110 2972.84,3082.16 C15.2@3046.02,3082.16
  Layer 4 - Bottom Layer w10: v1(2925,3110) 2925,3077.13 U7.14@2930,3072.13
NetC19_2: C19.2 U6.14 | length 71.8
  Layer 1 - Top Layer w10: C19.2@1748.5,215 v1(1785,215)
  Layer 4 - Bottom Layer w10: v1(1785,215) 1814.06,215 U6.14@1818.46,210.59
NetC25_1: C25.1 C26.1 R22.1 U10.6 | length 223.3
  Layer 4 - Bottom Layer w10: U10.6@3160.22,580.68 3160.22,647.29 C25.1@3144.51,663 C26.1@3144.51,718 3144.51,748 R22.1@3179.51,783
NetC27_1: C27.1 C28.1 U10.7 | length 145.9
  Layer 4 - Bottom Layer w10: U10.7@3185.81,580.68 3185.81,642.29 C27.1@3206.52,663 C28.1@3206.52,718
NetC29_1: C29.1 C30.1 U10.1 | length 208.1
  Layer 4 - Bottom Layer w10: U10.1@3210.49,415.32 3210.49,450.47 ; U10.1@3211.4,415.32 3211.4,449.55 3210.49,450.47 ; C30.1@3340.07,466.5 C29.1@3283.02,466.5 3281.52,468 3228.02,468 3210.49,450.47
NetC29_2: C29.2 C30.2 U10.8 | length 173
  Layer 4 - Bottom Layer w10: U10.8@3211.4,580.68 3211.4,546.39 3210.49,545.47 3227.95,528 3281.52,528 C29.2@3283.02,529.5 C30.2@3340.07,529.5
NetC31_1: C31.1 C32.1 C43.1 JMTI_-18V.1 U9.3 | length 136.2
  Layer 1 - Top Layer w20: C43.1@1876.57,3733.39 U9.3@2012.8,3733.39
NetC33_1: C33.1 L4.1 U10.4
NetC35_1: C35.1 R45.1 U9.1 | length 139.9
  Layer 1 - Top Layer w10: R45.1@1991.5,3855 2038.5,3855 C35.1@2058.5,3835 U9.1@2012.8,3789.29
NetC37_1: C37.1 R45.2 U9.8 | length 503.5
  Layer 1 - Top Layer w10: R45.2@1928.5,3855 1925,3855 1925,3829.14 1935,3819.14 1935,3799.82 1944.82,3790 v2(1945,3790) ; C37.1@2012.8,3560.48 U9.8@2012.8,3605.43 ; U9.8@2017.36,3610 v2(2064.31,3610)
  Layer 4 - Bottom Layer w10: v2(1945,3790) 1920,3765 1920,3610 v2(2064.31,3610)
NetC38_1: C38.1 C39.1 R41.1 R42.2 U9.6 | length 535.2
  Layer 1 - Top Layer w10: R41.1@1701.5,3470 C39.1@1701.51,3527.8 ; C39.1@1704.31,3525 1811.61,3525 1820,3533.39 1820,3630 1846.61,3656.61 U9.6@2012.8,3656.61 ; R42.2@1763.5,3465 C38.1@1763.5,3522.82
NetC38_2: C38.2 R40.1 U9.5 | length 353.7
  Layer 1 - Top Layer w10: R40.1@1701.51,3587.8 1758.52,3587.8 C38.2@1760.02,3589.3 1760.02,3595.02 1847.2,3682.2 U9.5@2012.8,3682.2
NetC39_2: C39.2 R40.2 | length 60
  Layer 1 - Top Layer w10: C39.2@1638.52,3527.8 R40.2@1638.52,3587.8
NetC40_2: C40.2 U9.16 | length 2.5
  Layer 1 - Top Layer w10: C40.2@2237.2,3825.71 C40.2@2239,3827.5
NetC45_1: C45.1 U11.6 | length 120.5
  Layer 1 - Top Layer w10: v1(2380,3045) 2380,3040.07 2385.42,3045.49 C45.1@2437.74,3045.49
  Layer 4 - Bottom Layer w10: v1(2380,3045) 2387.8,3037.2 U11.6@2432.4,3037.2
NetC46_2: C46.2 R43.1 R44.2 U11.2 | length 193.4
  Layer 4 - Bottom Layer w20: U11.2@2607.6,3062.8 2642.8,3062.8 2655.85,3075.85 R43.1@2680,3075.85 ; R44.2@2680,3014.55 R43.1@2680,3075.85 ; C46.2@2734.29,3075.85 R43.1@2680,3075.85
NetC83_1: C83.1 R99.1 | length 57
  Layer 1 - Top Layer w8: R99.1@1270,2286.24 C83.1@1270,2343.25
NetC83_2: C83.2 C317.2 FDA1.2 RDN2.1 RMFBN2.1 | length 270.2
  Layer 1 - Top Layer w8: RMFBN2.1@1331,2467.38 1328.37,2464.75 RDN2.1@1271.5,2464.75 1270,2463.25 C83.2@1270,2406.24 1330,2346.24 C317.2@1330,2343.25 1348.66,2324.59 FDA1.2@1384.88,2324.59
NetC86_1: C86.1 R101.1 R104.1 R212.2 | length 179
  Layer 1 - Top Layer w8: R212.2@1598.62,2339.75 1646.5,2339.75 C86.1@1655,2348.25 R101.1@1715,2348.25 1772.01,2348.25 R104.1@1773.5,2349.75
NetC86_2: C86.2 R101.2 RMFBN2.2 RMFBN.2 | length 558.5
  Layer 1 - Top Layer w8: RMFBN.2@1256.62,2520.55 RMFBN.2@1262.55,2514.62 ; C86.2@1654,2412.24 C86.2@1655,2411.24 R101.2@1715,2411.24
  Layer 1 - Top Layer w10: RMFBN.2@1262.55,2514.62 RMFBN2.2@1331,2514.62 1367.62,2514.62 1392,2539 1585,2539 1655,2469 1655,2413.24 C86.2@1654,2412.24
NetC87_1: C87.1 R100.1 R103.1 R211.2 | length 179
  Layer 1 - Top Layer w8: R211.2@1598.62,2289.75 1646.5,2289.75 C87.1@1655,2281.24 R100.1@1715,2281.24 1772.01,2281.24 R103.1@1773.5,2279.75
NetC87_2: C87.2 R100.2 RMFBP2.1 RMFBP.1 | length 557.4
  Layer 1 - Top Layer w8: C87.2@1654,2217.25 C87.2@1655,2218.25 R100.2@1715,2218.25
  Layer 1 - Top Layer w10: RMFBP.1@1256.62,2110 1324.62,2110 RMFBP2.1@1329,2114.38 1366.23,2114.38 1390.86,2089.75 1584.14,2089.75 1654,2159.6 C87.2@1654,2217.25
NetC88_2: C88.2 UADS1.13 UADS1.14
NetC89_1: C89.1 C315.1 R103.2 UADS1.10 | length 209.2
  Layer 1 - Top Layer w8: C89.1@1836.5,2224.75 R103.2@1836.5,2279.75 C315.1@1891.5,2279.75 ; C315.1@1895,2283.25 1916.65,2304.9 UADS1.10@1985.2,2304.9
NetC90_1: C90.1 C315.2 R104.2 UADS1.9 | length 209.2
  Layer 1 - Top Layer w8: C90.1@1836.5,2404.75 R104.2@1836.5,2349.75 C315.2@1891.5,2349.75 ; C315.2@1895,2346.24 1916.65,2324.59 UADS1.9@1985.2,2324.59
NetC91_2: C91.2 C287.1 L8.2 UADS1.12 | length 258.4
  Layer 1 - Top Layer w15: C91.2@1956.5,2169.75 1956.5,2216.24 1985.2,2244.94 UADS1.12@1985.2,2262.75
  Layer 1 - Top Layer w30: C91.2@1956.5,2169.75 1956.5,2108.25 C287.1@1965,2099.75 L8.2@1965,2019.75
NetC92_1: C92.1 C288.1 L9.2 UADS1.16 | length 245.6
  Layer 1 - Top Layer w10: UADS1.16@2069.84,2239.94 2069.84,2174.9 2088.5,2156.24 C92.1@2088.5,2154.75
  Layer 1 - Top Layer w30: C92.1@2088.5,2154.75 2088.5,2091.24 C288.1@2095,2084.75 L9.2@2095,2004.75
NetC93_1: C93.1 C289.1 R258.1 UADS1.3 | length 242
  Layer 1 - Top Layer w10: UADS1.3@2069.84,2389.55 2069.84,2449.59 2093.5,2473.25 C93.1@2093.5,2474.75
  Layer 1 - Top Layer w30: C93.1@2093.5,2474.75 2093.5,2536.24 C289.1@2085,2544.75 2093.5,2553.25 R258.1@2093.5,2614.75
NetC110_1: C110.1 R113.2 | length 55
  Layer 1 - Top Layer w8: C110.1@1203.5,1014.75 R113.2@1203.5,1069.75
NetC110_2: C110.2 C111.2 R114.1 RDP4.1 U1.4 | length 326.9
  Layer 1 - Top Layer w20: U1.4@1317.6,840.61 1284.13,840.61 1266.5,858.25 C110.2@1266.5,1014.75 C111.2@1323.5,1014.75 R114.1@1323.5,1069.75
NetC111_1: C111.1 R114.2 R115.1 U1.1 | length 180.3
  Layer 1 - Top Layer w8: R114.2@1386.5,1069.75 C111.1@1386.5,1014.75 ; U1.1@1392.4,948.88 1392.4,1008.84 C111.1@1386.5,1014.75 ; R115.1@1443.5,1014.75 C111.1@1386.5,1014.75
NetC113_1: C113.1 C114.2 R116.1 RDN4.1 U2.4 | length 324
  Layer 1 - Top Layer w10: U2.4@1317.6,1170.61 1281.06,1170.61 1266.18,1185.49 1266.18,1280.68 RDN4.1@1266.5,1281 C113.1@1266.5,1339.75 C114.2@1323.5,1339.75 R116.1@1323.5,1394.75
NetC113_2: C113.2 R112.2 | length 55
  Layer 1 - Top Layer w8: C113.2@1203.5,1339.75 R112.2@1203.5,1394.75
NetC114_1: C114.1 R116.2 R117.1 U2.1 | length 175.3
  Layer 1 - Top Layer w8: R116.2@1386.5,1394.75 C114.1@1386.5,1339.75 ; U2.1@1392.4,1278.88 1392.4,1304.75 1386.5,1310.65 C114.1@1386.5,1339.75 ; R117.1@1443.5,1339.75 C114.1@1386.5,1339.75
NetC117_1: C117.1 C335.2 R117.2 UADS2.9 | length 386.5
  Layer 1 - Top Layer w8: C117.1@1506.5,1394.75 R117.2@1506.5,1339.75 1547,1339.75 1610,1276.75 1610,1256.75 C335.2@1668.5,1198.24 ; C335.2@1670,1196.24 1691.65,1174.59 UADS2.9@1760.2,1174.59
NetC118_1: C118.1 C335.1 R115.2 UADS2.10 | length 364.4
  Layer 1 - Top Layer w8: C118.1@1506.5,1069.75 R115.2@1506.5,1014.75 1552,1014.75 C335.1@1668.5,1131.25 ; C335.1@1670,1133.25 1691.65,1154.9 UADS2.10@1760.2,1154.9
NetC119_1: C119.1 UADS2.13 UADS2.14
NetC120_2: C120.2 C306.1 L6.2 UADS2.12 | length 258.4
  Layer 1 - Top Layer w15: C120.2@1731.5,1019.75 1731.5,1066.24 1760.2,1094.94 UADS2.12@1760.2,1112.75
  Layer 1 - Top Layer w30: C120.2@1731.5,1019.75 1731.5,958.25 C306.1@1740,949.75 L6.2@1740,869.75
NetC121_1: C121.1 C307.1 L7.2 UADS2.16 | length 245.6
  Layer 1 - Top Layer w10: UADS2.16@1844.84,1089.94 1844.84,1024.9 1863.5,1006.24 C121.1@1863.5,1004.75
  Layer 1 - Top Layer w30: C121.1@1863.5,1004.75 1863.5,941.24 C307.1@1870,934.75 L7.2@1870,854.75
NetC122_1: C122.1 C308.1 R261.1 UADS2.3 | length 247.2
  Layer 1 - Top Layer w10: UADS2.3@1844.84,1239.55 C122.1@1844.84,1339.75
  Layer 1 - Top Layer w30: C122.1@1853.5,1339.75 1853.5,1401.24 1845,1409.75 1853.5,1418.25 R261.1@1853.5,1479.75
NetC316_1: C316.1 FDA1.4 | length 104.3
  Layer 1 - Top Layer w8: C316.1@1330,2223.25 1363.5,2223.25 1384.88,2244.63 FDA1.4@1384.88,2285.22
NetC316_2: C316.2 FDA1.3 R99.2 RDP2.1 RMFBP2.2 | length 267.6
  Layer 1 - Top Layer w8: RMFBP2.2@1329,2161.62 1325.62,2165 RDP2.1@1272.5,2165 1270,2167.5 R99.2@1270,2223.25 1330,2283.25 C316.2@1330,2286.24 1348.66,2304.9 FDA1.3@1384.88,2304.9
NetC317_1: C317.1 FDA1.1 | length 104.3
  Layer 1 - Top Layer w8: C317.1@1330,2406.24 1363.5,2406.24 1384.88,2384.86 FDA1.1@1384.88,2344.27
NetC319_1: C319.1 R215.1 U4.1 | length 129.5
  Layer 1 - Top Layer w15: U4.1@1049.13,1797.6 1055,1791.74 1055,1743.87 C319.1@1061.5,1737.38 1123.5,1737.38 R215.1@1125,1738.87
NetC319_2: C319.2 R216.1 U4.4 | length 235.2
  Layer 1 - Top Layer w15: U4.4@940.87,1872.41 977.28,1872.41 998.5,1851.19 C319.2@998.5,1737.38 R216.1@998.5,1682.38
NetC321_1: C321.1 R217.2 R218.1 TP28.1 U4.3 | length 276.7
  Layer 1 - Top Layer w15: U4.3@1049.13,1872.41 1077.4,1872.41 1088.87,1883.87 C321.1@1125,1883.87 R217.2@1180,1883.87 ; TP28.1@1180,1970 R217.2@1180,1883.87 ; R218.1@1235,1883.87 R217.2@1180,1883.87
NetC322_2: C322.2 R268.2 | length 67.4
  Layer 1 - Top Layer w10: R268.2@1935,2546.24 1960,2546.24 C322.2@1990,2516.24
NetC323_2: C323.2 R269.2 | length 65.4
  Layer 1 - Top Layer w10: R269.2@1710,1391.24 1740,1391.24 C323.2@1765,1366.24
NetC355_1: C355.1 C356.1 JSI_3.3V.1 L20.1
NetC357_1: C357.1 C358.1 C359.1 C360.1 L20.2 U3P8V.4 U3P8V.14 U3P8V.15 U3P8V.18 | length 619.3
  Layer 3 - PWR w10: v2(1020,305) 1070,255 v3(1106,255)
  Layer 3 - PWR w80: 725,125 760,125 765.29,125 825.29,65 980,65 1040,125 v2(1095,125) v2(1140,125)
  Layer 4 - Bottom Layer w10: v2@1029.61,306.77 U3P8V.18@1038.46,315.63 ; C360.1@1115,240 C360.1@1140,215
  other v2: 1095,95 715,120 745,120 775,120 740,150 1095,155
  other v3: 1140,95 710,150 770,150 1140,155
NetC361_1: C361.1 U3P8V.2 | length 120.7
  Layer 4 - Bottom Layer w10: C361.1@1003.5,495 1003.5,471.5 1015,460 1060,460 1073.9,446.1 U3P8V.2@1073.9,429.8
NetC361_2: C361.2 L21.1 U3P8V.9 | length 164.7
  Layer 4 - Bottom Layer w8: C361.2@1066.5,495 1090.63,470.87 1090.63,389.37 1108,372 1108.73,372 1114,366.73 1114,366 U3P8V.9@1125,355
NetC362_1: C362.1 RB3.1 U3P8V.22 | length 181.2
  Layer 4 - Bottom Layer w8: C362.1@910,398.62 RB3.1@910,456.38 ; C362.1@915.63,394.37 U3P8V.22@1038.46,394.37
  Layer 4 - Bottom Layer w10: U3P8V.22@1038.46,394.37 U3P8V.22@1038.46,395
NetC363_1: C363.1 R290.2 R291.2 U3P8V.21 | length 347
  Layer 1 - Top Layer w10: v2@1010,375 v2(1015,375)
  Layer 3 - PWR w10: v2(880,245) v2@1010,375
  Layer 4 - Bottom Layer w10: C363.1@920,188.62 R291.2@865,188.62 865,230 v2(880,245) 918.62,245 R290.2@920,246.38
NetC363_2: C363.2 C364.1 C366.1 JTI_3.3V.1 L21.2 R291.1 RB3.2 RES3V.1 | length 2534.4
  Layer 3 - PWR w10: v3(850,140) 835,140 805,170 805,500 910,605 1305,605 1470,440 v2(1470,370) ; v3(980,170) 880,170 855,195 855,465 v3(910,520) 970,580 1280,580 1430,430 v2(1430,370)
  Layer 3 - PWR w80: 1389.96,355 1485,355
  Layer 4 - Bottom Layer w10: R291.1@865,141.38 C363.2@920,141.38
  other v2: 1430,340 1470,340 1505,340 1505,370
NetC367_1: C367.1 C368.1 JSI_5V.1 L22.1
NetC369_1: C369.1 C370.1 C371.1 C372.1 L22.2 U5P5V.4 U5P5V.14 U5P5V.15 U5P5V.18 | length 100
  Layer 4 - Bottom Layer w10: U5P5V.15@3557.64,3654.8 3557.64,3687.64 ; 3565,3625 3626.54,3625 U5P5V.18@3626.54,3619.37
NetC373_1: C373.1 U5P5V.2 | length 114.7
  Layer 4 - Bottom Layer w10: U5P5V.2@3589.75,3503.85 U5P5V.2@3591.1,3505.2 3591.1,3478.9 3600,3470 3631.5,3470 C373.1@3661.5,3440
NetC373_2: C373.2 L23.1 U5P5V.9 | length 166.3
  Layer 4 - Bottom Layer w8: U5P5V.9@3535,3580 3575,3540 3575,3463.5 C373.2@3598.5,3440
NetC374_1: C374.1 R294.2 R295.2 U5P5V.21 | length 345.6
  Layer 4 - Bottom Layer w10: U5P5V.21@3626.54,3560.31 3629.33,3563.11 3645.8,3563.11 3653.27,3570.58 3653.27,3583.27 3695.13,3625.13 3695.13,3633.21 3729.05,3667.13 3729.05,3674.05 3730,3675 R294.2@3745,3688.62 3783.62,3688.62 3800,3705 R295.2@3800,3746.38 C374.1@3745,3746.38
NetC374_2: C374.2 C376.1 C378.1 JTI_5V.1 L23.2 R295.1 RB5.2 RES5V.1 | length 2441.5
  Layer 3 - PWR w10: 3420,3275 3445.2,3275 ; 3440,3255 3440,3269.8 3445.2,3275 ; v3(3685,3765) 3760,3765 3820,3705 3820,3485 3755,3420 v3(3755,3415) 3639,3299 3469.94,3299 3469.57,3299.37 3445.2,3275 ; v3(3830,3755) 3855,3730 3855,3470 3660,3275 3445.2,3275
  Layer 3 - PWR w80: v2@3175,3560 3175,3476 3356,3295 3400,3295 3420,3275 ; 3440,3255 3440,3145 3575,3145
  Layer 4 - Bottom Layer w10: C374.2@3745,3793.62 R295.1@3800,3793.62 3815,3778.62 3815,3773.08 3830,3758.08 v3(3830,3755)
  other v2: 3579,3125 3605,3125 3635,3125 3579,3155 3605,3155 3635,3155 3579,3190 3605,3190 3635,3190 3148,3562 3173,3562 3198,3562 3223,3562 3248,3562 3273,3562 3148,3587 3173,3587 3198,3587 3223,3587 3248,3587 3273,3587
NetC375_1: C375.1 RB5.1 U5P5V.22 | length 187.7
  Layer 4 - Bottom Layer w10: RB5.1@3755,3478.62 C375.1@3755,3536.38 ; C375.1@3755,3540 U5P5V.22@3627.17,3540 ; U5P5V.22@3627.17,3540 3626.54,3540 U5P5V.22@3626.54,3540.63 U5P5V.22@3627.17,3540
NetC379_1: C379.1 C380.1 JSI_18V.2 L24.1
NetC381_1: C381.1 C382.1 C383.1 C384.1 L24.2 U18P5V.4 U18P5V.14 U18P5V.15 U18P5V.18 | length 653
  Layer 3 - PWR w80: 555,2925 640,2840 927,2840 968,2881
  Layer 4 - Bottom Layer w10: U18P5V.18@878.46,3050.63 860,3032.17 860,3000 870,2990 950,2990 ; C384.1@955,2955 C384.1@980,2930
  other v2: 542,2896 565,2896 940,2900 985,2910 542,2922 565,2922 542,2950 565,2950
  other v3: 960,2910
NetC385_1: C385.1 U18P5V.2 | length 120.7
  Layer 4 - Bottom Layer w10: C385.1@843.5,3230 843.5,3206.5 861.42,3188.58 903.8,3188.58 913.9,3178.49 U18P5V.2@913.9,3164.8 U18P5V.2@915,3165.91
NetC385_2: C385.2 L25.1 U18P5V.9 | length 216.5
  Layer 4 - Bottom Layer w8: C385.2@906.5,3230 906.5,3208.5 929.79,3185.21 929.79,3120.15 959.94,3090 U18P5V.9@1014.29,3090
NetC387_1: C387.1 R297.2 R298.2 U18P5V.21 | length 354.8
  Layer 4 - Bottom Layer w10: C387.1@760,2923.62 R298.2@705,2923.62 705,2980 760,2980 775,2995 775,3006.22 851.73,3082.95 851.73,3099.42 859.2,3106.89 875.67,3106.89 U18P5V.21@878.46,3109.69
NetC387_2: C387.2 C389.1 C391.1 JTI_18V.1 L25.2 R298.1 | length 862.9
  Layer 3 - PWR w10: v2(655,2910) 911,2910 926,2925 951,2950 1230,2950 1305,3025 1305,3075
  Layer 4 - Bottom Layer w10: v2(655,2910) R298.1@705,2876.38 C387.2@760,2876.38
  other v2: 1280,3045 1305,3045 1280,3125 1305,3125
  other v3: 1280,3085 1305,3085
NetC388_1: C388.1 RB18.1 U18P5V.22 | length 188.9
  Layer 4 - Bottom Layer w10: RB18.1@750,3191.38 C388.1@750,3133.62 754.25,3129.37 846.09,3129.37 846.72,3130 878.46,3130 U18P5V.22@878.46,3129.37
NetC401_1: C401.1 C402.1 C408.1 JPRI_-18V.1 U401.12 U401.13 U401.14 | length 882.9
  Layer 3 - PWR w100: 2035,3420 2186,3420 2243,3477 2243,3685 2292,3734 2666,3734
  other v2: 2070,3402 2036,3403 2105,3403 2035,3436 2106,3436 2072,3437
NetC403_1: C403.1 U401.4 | length 106
  Layer 4 - Bottom Layer w10: U401.4@2521.14,3562.8 2521.14,3566.18 2597.32,3566.18 C403.1@2616,3547.5
NetC403_2: C403.2 C405.2 C406.2 C407.2 C408.2 JTI_-18V.3 R401.1 R404.1 U401.6 U401.10 U401.15 U401.16 U401.17@2405,3550 | length 1487.3
  Layer 4 - Bottom Layer w10: C407.2@2148.5,3495 2173.5,3470 2183.97,3470 2187.67,3466.3 2235.32,3466.3 2255.05,3486.02 U401.10@2288.86,3486.02 2338.07,3486.02 ; U401.16@2288.86,3639.57 U401.16@2289.61,3638.82 ; v4(2348.9,3475.2) 2338.07,3486.02 ; U401.17@2406.5,3457.99 v4(2423.7,3475.2) ; v4(2461.1,3512.6) U401.17@2462.09,3511.61 ; U401.6@2521.14,3511.61 2560,3511.61 2575,3496.61 2575,3445 ; C403.2@2681.5,3550 C405.2@2681.5,3485 2681.5,3451.5 2675,3445 2575,3445 ; 2338.07,3486.02 2375.47,3486.02 v4(2386.3,3475.2) 2386.3,3373.7 2415,3345 2560,3345 2575,3360 2575,3445
  Layer 4 - Bottom Layer w15: C408.2@2195,3684.96 2365,3685 2381.93,3668.07 U401.17@2381.93,3629.17 ; U401.15@2288.86,3613.98 2359.72,3613.98 v6(2386.3,3587.4) ; U401.16@2289.61,3638.82 2372.29,3638.82 U401.17@2381.93,3629.17 ; U401.17@2405,3606.1 v4(2386.3,3624.8) U401.17@2381.93,3629.17
  other v2: 2437,3334 2465,3335 2495,3335 2525,3335 2555,3335
  other v4: 2461.1,3475.2 2348.9,3512.6 2348.9,3550 2461.1,3550 2348.9,3587.4 2461.1,3587.4 2348.9,3624.8 2423.7,3624.8 2461.1,3624.8
  other v6: 2386.3,3512.6 2423.7,3512.6 2386.3,3550 2423.7,3550 2423.7,3587.4
NetC404_1: C404.1 U401.3 | length 99.3
  Layer 4 - Bottom Layer w15: U401.3@2521.14,3588.39 2584.88,3588.39 C404.1@2610,3613.5
NetC404_2: C404.2 L401.1 U401.1 U401.2 | length 108.5
  Layer 4 - Bottom Layer w15: U401.2@2521.14,3613.98 U401.1@2521.14,3639.57 2573.07,3639.57 C404.2@2595,3661.5
NetC407_1: C407.1 U401.11 | length 87.9
  Layer 4 - Bottom Layer w11: C407.1@2211.5,3495 2230.7,3514.2 2288.86,3514.2 U401.11@2288.86,3511.61
NetC409_2: C409.2 R401.2 R402.1 U401.9 | length 230.6
  Layer 4 - Bottom Layer w10: R402.1@2211.5,3430 2288.86,3430 ; C409.2@2216.5,3355 R402.1@2216.5,3420 ; U401.9@2288.86,3460.43 2288.86,3430 ; R401.2@2331.69,3408.05 2319.75,3420 2288.86,3420 2288.86,3430
NetC452_1: C452.1 C457.1 C458.1 C459.1 C461.1 R457.1 R489.2 R492.2 R494.2 | length 105.3
  Layer 1 - Top Layer w40: C457.1@413.5,1919.75 413.5,1958.25 435,1979.75 R457.1@471.38,1979.75
NetC452_2: C452.2 R489.1 U415.1 | length 143.7
  Layer 1 - Top Layer w15: C452.2@489.55,1763.74 C452.2@489.83,1764.02 ; C452.2@490,1749.75 490,1676.24 R489.1@491.5,1674.75 515.87,1650.38 U415.1@515.87,1617.15
NetC453_1: C453.1 R485.2 U414.3 | length 115
  Layer 1 - Top Layer w15: U414.3@884.13,1567.15 C453.1@944.09,1567.15 ; C453.1@945,1566.24 R485.2@1000,1566.24
NetC454_1: C454.1 R486.2 R488.2 U415.3 | length 557.5
  Layer 1 - Top Layer w20: v5(735,1739.75) C454.1@778.5,1739.75 R488.2@778.5,1684.75 R486.2@778.5,1629.75
  Layer 4 - Bottom Layer w20: v2(534.83,1539.02) 516.8,1557.04 516.8,1701.55 555,1739.75 v5(735,1739.75)
NetC460_1: C460.1 R486.1 U414.1 | length 319.8
  Layer 1 - Top Layer w15: C460.1@710,1478.25 761.5,1529.75 820.2,1529.75 ; R486.1@841.5,1629.75 820.2,1608.45 820.2,1529.75 ; U414.1@884.13,1492.34 857.6,1492.34 820.2,1529.75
